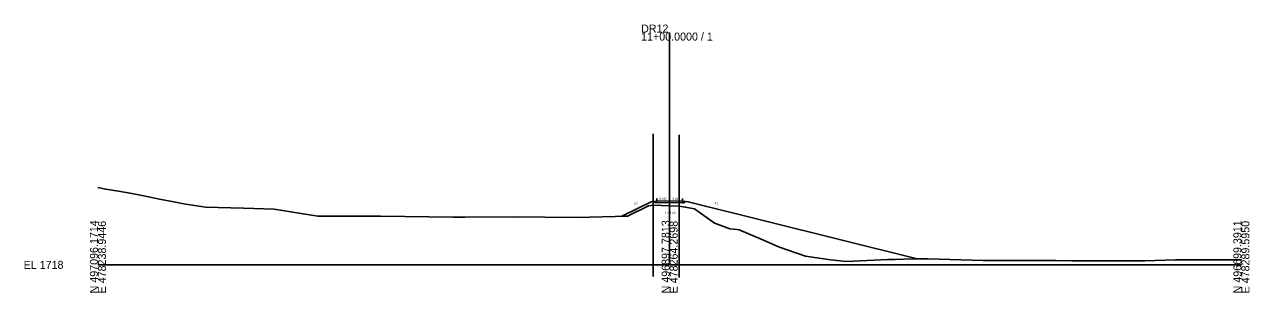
# Model space of a CAD drawing. Extents: x -26 to 403, y -10 to 3574.
# Drawn here: x -25.7 to 402.8, y 1990.3 to 2084.2 of the extents above; entities that cross this region are included whole.
import ezdxf

# ---------------------------------------------------------------- set-up
doc = ezdxf.new("R2010")
doc.units = 0
for name, color, linetype in [('Exist Cross Section Cell', 7, 'Continuous'), ('Exist XS Center Line Elevation Label', 7, 'Continuous'), ('Exist XS Ground Line', 7, 'Continuous'), ('Prop XS Earthwork Shape', 7, 'Continuous'), ('Prop XS EOT Tick Mark', 7, 'Continuous'), ('Prop XS Finish Grade', 7, 'Continuous'), ('Prop XS Finish Grade Earthwork', 7, 'Continuous'), ('Prop XS Finish Grade Pavement', 7, 'Continuous'), ('Prop XS Pvmt Edge Slope', 7, 'Continuous'), ('Prop XS SE Text', 7, 'Continuous'), ('Prop XS Shoulder Borrow Shape', 7, 'Continuous'), ('Prop XS Side Slope Text', 7, 'Continuous'), ('Prop XS Subgrade Earthwork', 7, 'Continuous'), ('Scratch_Level_1', 7, 'Continuous'), ('Scratch_Level_4', 7, 'Continuous')]:
    doc.layers.add(name, color=color, linetype=linetype)

msp = doc.modelspace()

# ---------------------------------------------------------------- linework, layer by layer
at = {"layer": 'Exist Cross Section Cell'}
for p, q in [((200, 2000), (200, 2081.34)), ((0, 2000), (200, 2000)), ((200, 2000), (400, 2000))]:
    msp.add_line(p, q, dxfattribs=at)
at = {"layer": 'Exist XS Ground Line'}
msp.add_lwpolyline([(0, 2027.11), (2.75, 2026.5), (7.15, 2025.79), (11.86, 2024.93), (16.09, 2024.12), (21.56, 2023.01), (26.53, 2022.03), (30.08, 2021.38), (37.57, 2020.24), (50.89, 2019.9), (61.61, 2019.55), (67.47, 2018.53), (76.97, 2017.07), (80.12, 2017.08), (80.63, 2017.07), (98.82, 2017.09), (124.26, 2016.73), (128.35, 2016.75), (145.28, 2016.78), (167.54, 2016.54), (185.34, 2017.09), (185.76, 2017.28), (192.65, 2020.61), (194.31, 2020.87), (200, 2020.68), (203.35, 2020.57), (205.43, 2020.25), (208.66, 2019.63), (215.24, 2014.9), (215.7, 2014.61), (216.44, 2014.35), (221.02, 2012.59), (223.58, 2012.36), (224.31, 2012.28), (227.33, 2011.02), (232.8, 2008.62), (237.85, 2006.4), (238.47, 2006.25), (241.13, 2005.28), (247.56, 2003.08), (256.23, 2001.72), (261.9, 2001.17), (276.29, 2001.82), (278.91, 2001.84), (284.86, 2002.07), (290.46, 2002.13), (309.68, 2001.57), (310.84, 2001.57), (335.13, 2001.48), (340.7, 2001.46), (366.18, 2001.37), (376.9, 2001.81), (400, 2001.72)], dxfattribs=at)
at = {"layer": 'Prop XS Earthwork Shape'}
msp.add_lwpolyline([(183.31, 2017.02), (185.34, 2017.09), (185.76, 2017.28), (192.65, 2020.61), (194.31, 2020.87), (200, 2020.68), (203.35, 2020.57), (205.43, 2020.25), (208.66, 2019.63), (215.24, 2014.9), (215.7, 2014.61), (216.44, 2014.35), (221.02, 2012.59), (223.58, 2012.36), (224.31, 2012.28), (227.33, 2011.02), (232.8, 2008.62), (237.85, 2006.4), (238.47, 2006.25), (241.13, 2005.28), (247.56, 2003.08), (256.23, 2001.72), (261.9, 2001.17), (276.29, 2001.82), (278.91, 2001.84), (284.86, 2002.07), (286.6, 2002.09), (206.5, 2022.12), (205.52, 2022.2), (205.05, 2021.72), (204.5, 2021.74), (200, 2021.83), (194.95, 2021.72), (194.48, 2022.2), (193.5, 2022.12)], close=True, dxfattribs=at)
at = {"layer": 'Prop XS EOT Tick Mark'}
for p, q in [((195.5, 2022.28), (195.5, 2023.28)), ((204.5, 2022.28), (204.5, 2023.28))]:
    msp.add_line(p, q, dxfattribs=at)
at = {"layer": 'Prop XS Finish Grade'}
for p, q in [((195.5, 2022.28), (194.48, 2022.2)), ((204.5, 2022.28), (205.52, 2022.2))]:
    msp.add_line(p, q, dxfattribs=at)
at = {"layer": 'Prop XS Finish Grade Earthwork'}
for p, q in [((193.5, 2022.12), (183.31, 2017.02)), ((194.48, 2022.2), (193.5, 2022.12)), ((205.52, 2022.2), (206.5, 2022.12)), ((206.5, 2022.12), (286.6, 2002.09))]:
    msp.add_line(p, q, dxfattribs=at)
at = {"layer": 'Prop XS Finish Grade Pavement'}
for p, q in [((195.5, 2022.28), (200, 2022.37)), ((200, 2022.37), (204.5, 2022.28))]:
    msp.add_line(p, q, dxfattribs=at)
at = {"layer": 'Prop XS Pvmt Edge Slope'}
for p, q in [((195.5, 2022.28), (194.95, 2021.72)), ((204.5, 2022.28), (205.05, 2021.72))]:
    msp.add_line(p, q, dxfattribs=at)
at = {"layer": 'Prop XS Shoulder Borrow Shape'}
for points in [[(195.5, 2022.28), (194.48, 2022.2), (194.95, 2021.72)], [(204.5, 2022.28), (205.52, 2022.2), (205.05, 2021.72)]]:
    msp.add_lwpolyline(points, close=True, dxfattribs=at)
at = {"layer": 'Prop XS Subgrade Earthwork'}
for p, q in [((194.95, 2021.72), (194.48, 2022.2)), ((200, 2021.83), (194.95, 2021.72)), ((200, 2021.83), (204.5, 2021.74)), ((204.5, 2021.74), (205.05, 2021.72)), ((205.05, 2021.72), (205.52, 2022.2))]:
    msp.add_line(p, q, dxfattribs=at)
at = {"layer": 'Scratch_Level_1'}
for p, q in [((194.22, 2045.88), (194.22, 1995.88)), ((203.35, 2045.57), (203.35, 1995.57))]:
    msp.add_line(p, q, dxfattribs=at)
at = {"layer": 'Scratch_Level_4'}
for q in [(233.64, 2015.33), (286.6, 2002.09)]:
    msp.add_line((206.5, 2022.12), q, dxfattribs=at)

# ---------------------------------------------------------------- texts
at = {"layer": 'Exist Cross Section Cell'}
for s, p in [('DR12', (190, 2081.34)), ('11+00.0000 / 1', (190, 2078.54)), ('EL 1718', (-26, 1998.6))]:
    msp.add_text(s, height=2.8, dxfattribs=at).set_placement(p)
for s, p in [('N 497096.1714', (0, 1990)), ('E 478238.9446', (2.8, 1990)), ('N 496897.7813', (200, 1990)), ('E 478264.2698', (202.8, 1990)), ('N 496699.3911', (400, 1990)), ('E 478289.5950', (402.8, 1990))]:
    msp.add_text(s, height=2.8, rotation=90, dxfattribs=at).set_placement(p)
at = {"layer": 'Exist XS Center Line Elevation Label'}
msp.add_text('1738.68', height=0.75, dxfattribs=at).set_placement((198.25, 2017.93))
at = {"layer": 'Prop XS SE Text'}
for rotation, p in [(1.1458, (196.46, 2022.8)), (358.8542, (200.96, 2022.85))]:
    msp.add_text('0.020', height=0.75, rotation=rotation, dxfattribs=at).set_placement(p)
at = {"layer": 'Prop XS Side Slope Text'}
for s, rotation, p in [('2:1', 26.5651, (187.73, 2020.91)), ('4:1', 345.9638, (215.65, 2021.38))]:
    msp.add_text(s, height=0.75, rotation=rotation, dxfattribs=at).set_placement(p)

doc.saveas('drawing.dxf')
